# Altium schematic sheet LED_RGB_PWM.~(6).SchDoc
size A4
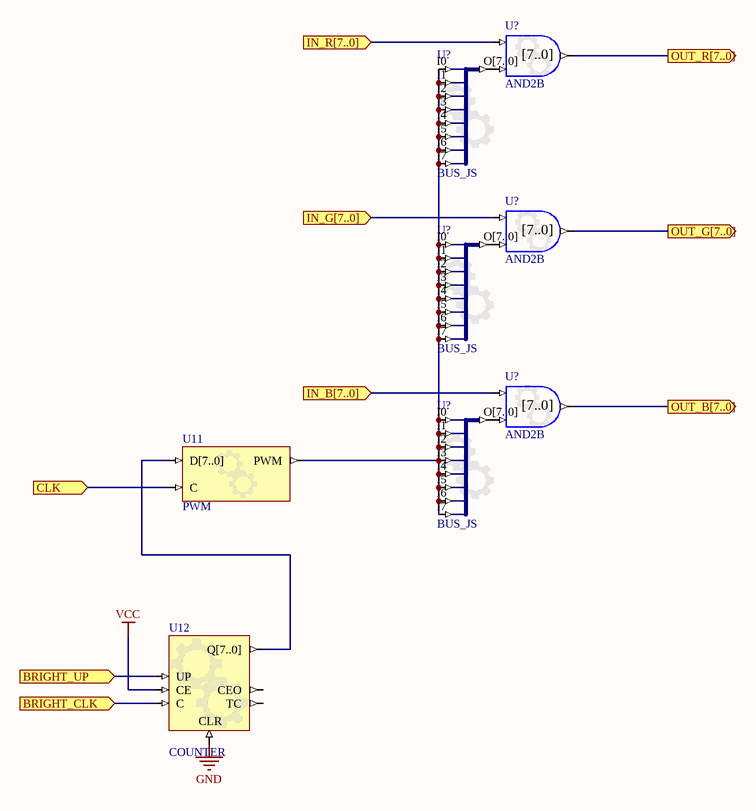
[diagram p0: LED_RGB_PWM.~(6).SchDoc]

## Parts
(Parts that share a designator on the sheet are numbered #1, #2 ... from top to bottom, then left to right.)
U11  PWM
U12  COUNTER
U?#1  AND2B
U?#2  BUS_JS
U?#3  AND2B
U?#4  BUS_JS
U?#5  AND2B
U?#6  BUS_JS

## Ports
BRIGHT_CLK (in), BRIGHT_UP (in), CLK (in), IN_B[7..0] (in), IN_G[7..0] (in), IN_R[7..0] (in), OUT_B[7..0] (out), OUT_G[7..0] (out), OUT_R[7..0] (out)

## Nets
GND: U12.CLR
VCC: U12.CE
BRIGHT_CLK: U12.C ; port BRIGHT_CLK
BRIGHT_UP: U12.UP ; port BRIGHT_UP
CLK: U11.C ; port CLK
NetU11_PWM: U11.PWM U?#2.I0 U?#2.I1 U?#2.I2 U?#2.I3 U?#2.I4 U?#2.I5 U?#2.I6 U?#2.I7 U?#4.I0 U?#4.I1 U?#4.I2 U?#4.I3 U?#4.I4 U?#4.I5 U?#4.I6 U?#4.I7 U?#6.I0 U?#6.I1 U?#6.I2 U?#6.I3 U?#6.I4 U?#6.I5 U?#6.I6 U?#6.I7
NetU?#1_I1_B[7..0]: U?#1.I1_B[7..0] U?#2.O[7..0]
NetU?#3_I1_B[7..0]: U?#3.I1_B[7..0] U?#4.O[7..0]
NetU?#5_I1_B[7..0]: U?#5.I1_B[7..0] U?#6.O[7..0]

Not connected (* = marked no-connect by the designer): U11 D[7..0]; U12 CEO Q[7..0] TC; U?#1 I0_B[7..0] O[7..0]; U?#3 I0_B[7..0] O[7..0]; U?#5 I0_B[7..0] O[7..0]

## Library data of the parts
U11 = PWM: Configurable PWM; ConfiguratorName: GENERIC_PWM; ConfigurationParameters: {}Version[1.0]{}Width[8]{}Prescaler[1]{}
U12 = COUNTER: Configurable Counter; ConfiguratorName: GENERIC_COUNTER; ConfigurationParameters: {}Version[1.0]{}Type[Binary]{}SyncReset[False]{}NegativeClockEdge[False]{}FixedDirection[False]{}IsIncrement[False]{}SignalWidth[8]{}MaxValue[255]{}BusOutput[True]{}Loadable[False]{}BusInput[False]{}
U?#1 U?#3 U?#5 = GATE: Configurable Generic Gate; ConfiguratorName: GENERIC_GATE; ConfigurationParameters: {}Version[1.1]{}GateKind[AND]{}BusInput[False]{}GateInputType[Bus]{}GateOutputOption[Normal]{}BusWidth[8]{}RegisterOutputs[False]{}NegativeClockEdge[False]{}InputCount[2]{}InputInvert0[False]{}InputInvert1[False]{}
U?#2 U?#4 U?#6 = BUS_JS: Configurable Bus Joiner/Splitter; ConfiguratorName: GENERIC_BUS_JS; ConfigurationParameters: {}Version[1.1]{}SplitterJoinerType[Joiner]{}SignalCount[8]{}SignalWidth0[1]{}GapBelow0[1000000]{}ConnectionType0[Pin]{}SignalWidth1[1]{}GapBelow1[1000000]{}ConnectionType1[Pin]{}SignalWidth2[1]{}GapBelow2[1000000]{}ConnectionType2[Pin]{}SignalWidth3[1]{}GapBelow3[1000000]{}ConnectionType3[Pin]{}SignalWidth4[1]{}GapBelow4[1000000]{}ConnectionType4[Pin]{}SignalWidth5[1]{}GapBelow5[1000000]{}ConnectionType5[Pin]{}SignalWidth6[1]{}GapBelow6[1000000]{}ConnectionType6[Pin]{}SignalWidth7[1]{}GapBelow7[1000000]{}ConnectionType7[Pin]{}ShowPinNames[True]{}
